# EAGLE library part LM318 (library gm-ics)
OP AMP
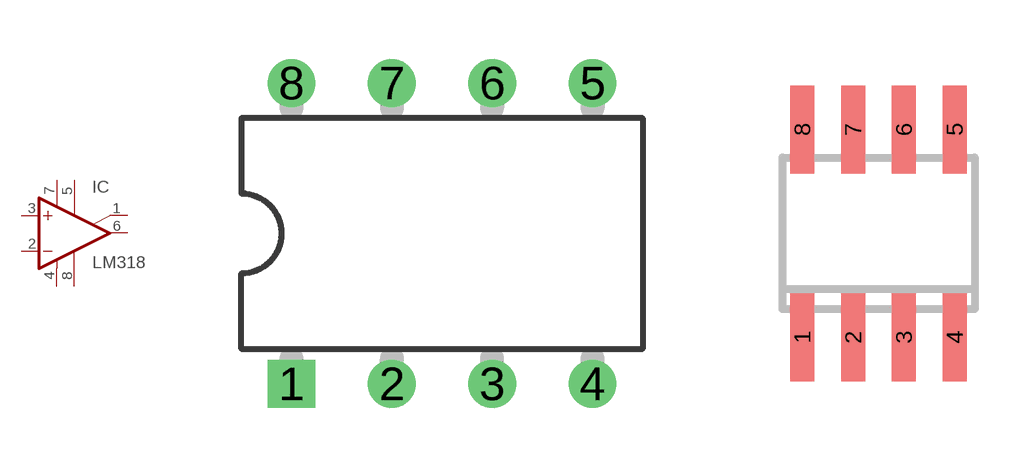
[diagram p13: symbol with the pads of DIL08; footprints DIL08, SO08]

Designator prefix IC

## LM318N  [DIL08]
1  ON/CMP  pas
2  -IN  in
3  +IN  in
4  V-  pwr
5  ON  pas
6  OUT  out
7  V+  pwr
8  CMP  pas

## LM318D  [SO08]
Pads as for DIL08

## Footprint DIL08 (pad centres in mm)
Dual In Line Package
drill 0.7 square: 1 -3.81,-3.81
drill 0.7 round: 2 -1.27,-3.81; 3 1.27,-3.81; 4 3.81,-3.81; 5 3.81,3.81; 6 1.27,3.81; 7 -1.27,3.81; 8 -3.81,3.81

## Footprint SO08 (pad centres in mm)
Small Outline Package 8 NS Package M08A
smd 0.6 x 2.2: 1 -1.905,-2.6; 2 -0.635,-2.6; 3 0.635,-2.6; 4 1.905,-2.6; 5 1.905,2.6; 6 0.635,2.6; 7 -0.635,2.6; 8 -1.905,2.6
